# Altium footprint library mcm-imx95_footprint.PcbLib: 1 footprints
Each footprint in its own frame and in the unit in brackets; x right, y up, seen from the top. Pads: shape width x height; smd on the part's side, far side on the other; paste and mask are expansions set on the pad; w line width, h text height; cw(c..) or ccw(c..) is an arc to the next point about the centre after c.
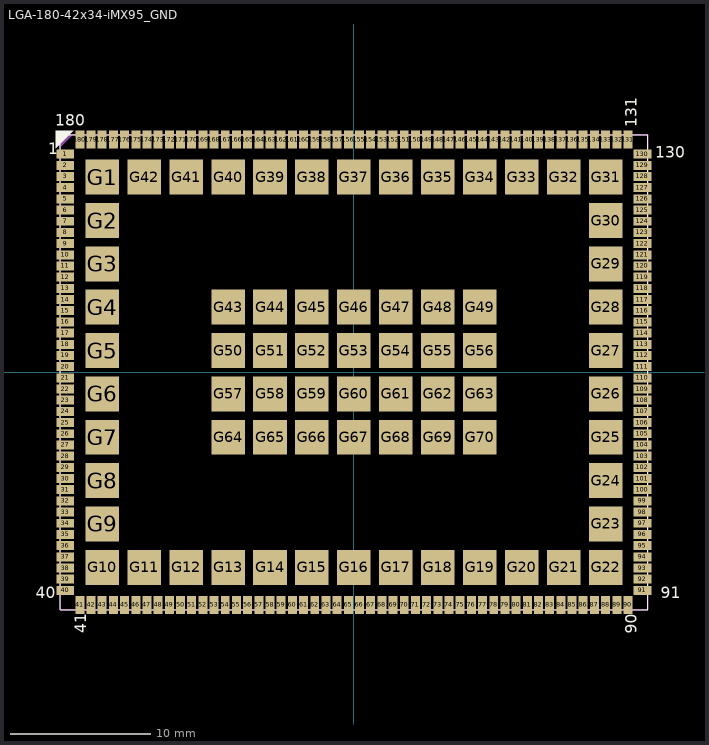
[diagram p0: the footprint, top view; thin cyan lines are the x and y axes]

## LGA-180-42x34-iMX95_GND [mm]
height 2
pads (250):
  rrect0% 1.275x0.64 smd paste-2539.97 mask+0: 1(-20.638,15.6) 2(-20.638,14.8) 3(-20.638,14) 4(-20.638,13.2) 5(-20.638,12.4) 6(-20.638,11.6) 7(-20.638,10.8) 8(-20.638,10) 9(-20.638,9.2) 10(-20.638,8.4) 11(-20.638,7.6) 12(-20.638,6.8) 13(-20.638,6) 14(-20.638,5.2) 15(-20.638,4.4) 16(-20.638,3.6) 17(-20.638,2.8) 18(-20.638,2) 19(-20.638,1.2) 20(-20.638,0.4) 21(-20.638,-0.4) 22(-20.638,-1.2) 23(-20.638,-2) 24(-20.638,-2.8) 25(-20.638,-3.6) 26(-20.638,-4.4) 27(-20.638,-5.2) 28(-20.638,-6) 29(-20.638,-6.8) 30(-20.638,-7.6) 31(-20.638,-8.4) 32(-20.638,-9.2) 33(-20.638,-10) 34(-20.638,-10.8) 35(-20.638,-11.6) 36(-20.638,-12.4) 37(-20.638,-13.2) 38(-20.638,-14) 39(-20.638,-14.8) 40(-20.638,-15.6) 91(20.638,-15.6) 92(20.638,-14.8) 93(20.638,-14) 94(20.638,-13.2) 95(20.638,-12.4) 96(20.638,-11.6) 97(20.638,-10.8) 98(20.638,-10) 99(20.638,-9.2) 100(20.638,-8.4) 101(20.638,-7.6) 102(20.638,-6.8) 103(20.638,-6) 104(20.638,-5.2) 105(20.638,-4.4) 106(20.638,-3.6) 107(20.638,-2.8) 108(20.638,-2) 109(20.638,-1.2) 110(20.638,-0.4) 111(20.638,0.4) 112(20.638,1.2) 113(20.638,2) 114(20.638,2.8) 115(20.638,3.6) 116(20.638,4.4) 117(20.638,5.2) 118(20.638,6) 119(20.638,6.8) 120(20.638,7.6) 121(20.638,8.4) 122(20.638,9.2) 123(20.638,10) 124(20.638,10.8) 125(20.638,11.6) 126(20.638,12.4) 127(20.638,13.2) 128(20.638,14) 129(20.638,14.8) 130(20.638,15.6)
  rrect0% 0.64x1.275 smd paste-2539.97 mask+0: 41(-19.6,-16.638) 42(-18.8,-16.638) 43(-18,-16.638) 44(-17.2,-16.638) 45(-16.4,-16.638) 46(-15.6,-16.638) 47(-14.8,-16.638) 48(-14,-16.638) 49(-13.2,-16.638) 50(-12.4,-16.638) 51(-11.6,-16.638) 52(-10.8,-16.638) 53(-10,-16.638) 54(-9.2,-16.638) 55(-8.4,-16.638) 56(-7.6,-16.638) 57(-6.8,-16.638) 58(-6,-16.638) 59(-5.2,-16.638) 60(-4.4,-16.638) 61(-3.6,-16.638) 62(-2.8,-16.638) 63(-2,-16.638) 64(-1.2,-16.638) 65(-0.4,-16.638) 66(0.4,-16.638) 67(1.2,-16.638) 68(2,-16.638) 69(2.8,-16.638) 70(3.6,-16.638) 71(4.4,-16.638) 72(5.2,-16.638) 73(6,-16.638) 74(6.8,-16.638) 75(7.6,-16.638) 76(8.4,-16.638) 77(9.2,-16.638) 78(10,-16.638) 79(10.8,-16.638) 80(11.6,-16.638) 81(12.4,-16.638) 82(13.2,-16.638) 83(14,-16.638) 84(14.8,-16.638) 85(15.6,-16.638) 86(16.4,-16.638) 87(17.2,-16.638) 88(18,-16.638) 89(18.8,-16.638) 90(19.6,-16.638) 131(19.6,16.638) 132(18.8,16.638) 133(18,16.638) 134(17.2,16.638) 135(16.4,16.638) 136(15.6,16.638) 137(14.8,16.638) 138(14,16.638) 139(13.2,16.638) 140(12.4,16.638) 141(11.6,16.638) 142(10.8,16.638) 143(10,16.638) 144(9.2,16.638) 145(8.4,16.638) 146(7.6,16.638) 147(6.8,16.638) 148(6,16.638) 149(5.2,16.638) 150(4.4,16.638) 151(3.6,16.638) 152(2.8,16.638) 153(2,16.638) 154(1.2,16.638) 155(0.4,16.638) 156(-0.4,16.638) 157(-1.2,16.638) 158(-2,16.638) 159(-2.8,16.638) 160(-3.6,16.638) 161(-4.4,16.638) 162(-5.2,16.638) 163(-6,16.638) 164(-6.8,16.638) 165(-7.6,16.638) 166(-8.4,16.638) 167(-9.2,16.638) 168(-10,16.638) 169(-10.8,16.638) 170(-11.6,16.638) 171(-12.4,16.638) 172(-13.2,16.638) 173(-14,16.638) 174(-14.8,16.638) 175(-15.6,16.638) 176(-16.4,16.638) 177(-17.2,16.638) 178(-18,16.638) 179(-18.8,16.638) 180(-19.6,16.638)
  rrect0% 2.4x2.5 smd paste-0.25 mask+0.025: G1(-18,13.95) G2(-18,10.85) G3(-18,7.75) G4(-18,4.65) G5(-18,1.55) G6(-18,-1.55) G7(-18,-4.65) G8(-18,-7.75) G9(-18,-10.85) G10(-18,-13.95) G11(-15,-13.95) G12(-12,-13.95) G13(-9,-13.95) G14(-6,-13.95) G15(-3,-13.95) G16(0,-13.95) G17(3,-13.95) G18(6,-13.95) G19(9,-13.95) G20(12,-13.95) G21(15,-13.95) G22(18,-13.95) G23(18,-10.85) G24(18,-7.75) G25(18,-4.65) G26(18,-1.55) G27(18,1.55) G28(18,4.65) G29(18,7.75) G30(18,10.85) G31(18,13.95) G32(15,13.95) G33(12,13.95) G34(9,13.95) G35(6,13.95) G36(3,13.95) G37(0,13.95) G38(-3,13.95) G39(-6,13.95) G40(-9,13.95) G41(-12,13.95) G42(-15,13.95) G43(-9,4.65) G44(-6,4.65) G45(-3,4.65) G46(0,4.65) G47(3,4.65) G48(6,4.65) G49(9,4.65) G50(-9,1.55) G51(-6,1.55) G52(-3,1.55) G53(0,1.55) G54(3,1.55) G55(6,1.55) G56(9,1.55) G57(-9,-1.55) G58(-6,-1.55) G59(-3,-1.55) G60(0,-1.55) G61(3,-1.55) G62(6,-1.55) G63(9,-1.55) G64(-9,-4.65) G65(-6,-4.65) G66(-3,-4.65) G67(0,-4.65) G68(3,-4.65) G69(6,-4.65) G70(9,-4.65)
Top Overlay:
  region: -20.066,17.272 -21.336,16.002 -21.336,17.272
  lines w0: -21,-17 21,-17 21,17 -21,17 -21,-17
  text "1" at -21.844,15.602 h0.8
  text "180" at -21.355,17.634 h0.8
  text "40" at -22.749,-16.148 h0.8
  text "131" at 20.212,17.514 h0.8
  text "130" at 21.568,15.348 h0.8
  text "91" at 21.962,-16.148 h0.8
  text "90" at 20.212,-18.685 h0.8
  text "41" at -19.158,-18.678 h0.8
Top Paste:
  drawing of 180 lines, arcs and shapes, not listed
Top Assembly:
  region: -20.066,17.018 -21.082,17.018 -21.082,16.002
  lines w0.1: -21,-17 21,-17 21,17 -21,17 -21,-17
Top Courtyard:
  lines w0: -21,-17 21,-17 21,17 -21,17 -21,-17
3D body: height 10, standoff 2, extent -21,-17 21,17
